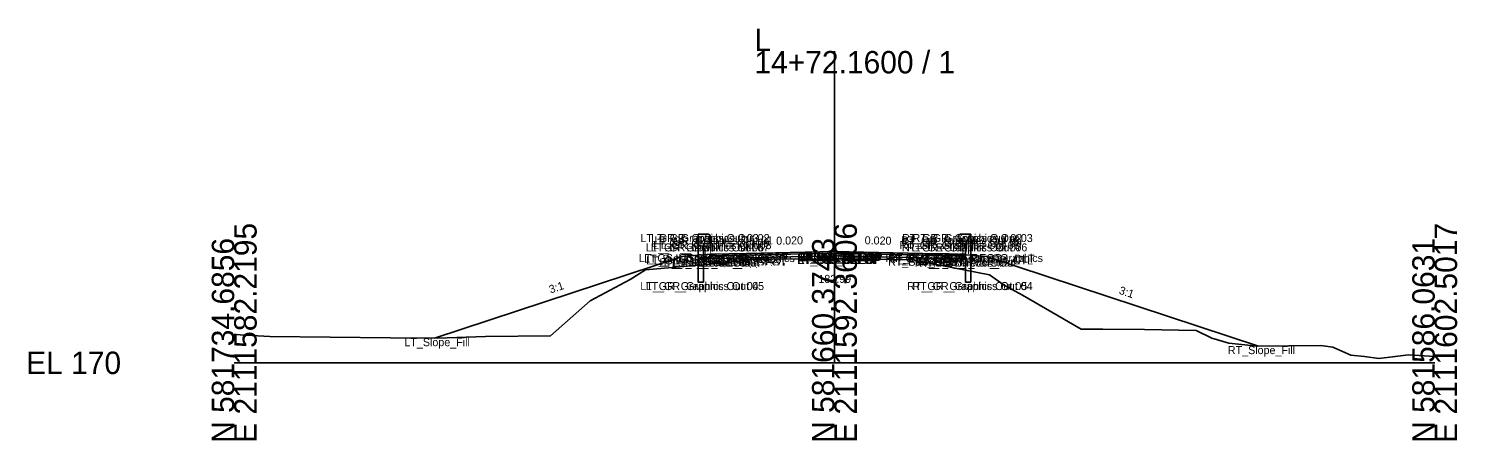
# Model space of a CAD drawing. Extents: x -26 to 3453, y -333 to 9539.
# Drawn here: x 3274.3 to 3452.8, y 490.3 to 541.8 of the extents above; entities that cross this region are included whole.
import ezdxf

# ---------------------------------------------------------------- set-up
doc = ezdxf.new("R2010")
doc.units = 0
for name, color, linetype in [('Default', 7, 'Continuous'), ('Exist Cross Section Cell', 7, 'Continuous'), ('Exist XS Ground Line', 7, 'Continuous'), ('Prop CMT Guardrail Graphics', 7, 'Continuous'), ('Prop CMT Pvmt Course 1', 7, 'Continuous'), ('Prop CMT Pvmt Course 2', 7, 'Continuous'), ('Prop CMT Pvmt Course 3', 7, 'Continuous'), ('Prop CMT Pvmt Surface', 7, 'Continuous'), ('Prop CMT Pvmt Surface Shoulder', 7, 'Continuous'), ('Prop CMT Shld Paved Course 1', 7, 'Continuous'), ('Prop CMT Shld Paved Course 2', 7, 'Continuous'), ('Prop CMT Shld Paved Course 3', 7, 'Continuous'), ('Prop CMT Slope Grass', 7, 'Continuous'), ('Prop CMT Subgrade Earthwork', 7, 'Continuous'), ('Prop XS SE Text', 7, 'Continuous'), ('Prop XS Side Slope Text', 7, 'Continuous'), ('Scratch_Level_0', 7, 'Continuous')]:
    doc.layers.add(name, color=color, linetype=linetype)

msp = doc.modelspace()

# ---------------------------------------------------------------- linework, layer by layer
at = {"layer": 'Exist Cross Section Cell'}
for p, q in [((3375, 500), (3375, 538.96)), ((3300, 500), (3375, 500)), ((3375, 500), (3450, 500))]:
    msp.add_line(p, q, dxfattribs=at)
at = {"layer": 'Exist XS Ground Line'}
msp.add_lwpolyline([(3300, 503.55), (3304.47, 503.31), (3319.51, 503.13), (3325.42, 503.08), (3331.39, 503.27), (3339.52, 503.36), (3344.49, 507.76), (3349.48, 510.4), (3351.38, 511.61), (3359.51, 512.34), (3365, 512.95), (3367.11, 512.96), (3374.8, 512.99), (3376.91, 512.98), (3384.74, 512.88), (3386.65, 512.51), (3394.36, 510.98), (3396.22, 509.7), (3398.48, 508.44), (3405.82, 504.2), (3408.53, 504.2), (3413.76, 504.16), (3420.21, 504.03), (3422.17, 503.07), (3424.27, 502.47), (3427.86, 502.09), (3435.69, 502.18), (3436.06, 502.12), (3437.26, 501.96), (3439.52, 500.94), (3441.23, 500.78), (3443.01, 500.54), (3444.72, 500.75), (3446.74, 500.99), (3450, 500.81)], dxfattribs=at)
at = {"layer": 'Prop CMT Guardrail Graphics'}
for points in [[(3357.97, 510.09), (3357.97, 516.09)], [(3357.97, 516.09), (3359.3, 516.09), (3359.57, 515.79)], [(3392.03, 516.09), (3390.7, 516.09), (3390.43, 515.79)], [(3392.03, 510.09), (3392.03, 516.09)], [(3359.57, 515.21), (3359.3, 514.92), (3358.64, 514.92)], [(3358.64, 514.92), (3358.64, 510.09)], [(3359.57, 515.79), (3359.3, 515.5)], [(3359.3, 515.5), (3359.57, 515.21)], [(3390.43, 515.79), (3390.7, 515.5)], [(3390.7, 515.5), (3390.43, 515.21)], [(3390.43, 515.21), (3390.7, 514.92), (3391.36, 514.92)], [(3391.36, 514.92), (3391.36, 510.09)], [(3358.64, 510.09), (3357.97, 510.09)], [(3391.36, 510.09), (3392.03, 510.09)]]:
    msp.add_lwpolyline(points, dxfattribs=at)
at = {"layer": 'Prop CMT Pvmt Course 1'}
for points in [[(3375, 513.9), (3364, 513.68)], [(3364, 513.47), (3375, 513.69)], [(3364, 513.68), (3364, 513.47)], [(3375, 513.69), (3375, 513.9)], [(3375, 513.9), (3386, 513.68)], [(3375, 513.69), (3375, 513.9)], [(3386, 513.47), (3375, 513.69)], [(3386, 513.68), (3386, 513.47)]]:
    msp.add_lwpolyline(points, dxfattribs=at)
msp.add_lwpolyline([(3375, 513.69), (3375, 513.77), (3375, 513.77), (3375, 513.69)], close=True, dxfattribs=at)
msp.add_lwpolyline([(3375, 513.69), (3375, 513.77), (3375, 513.77), (3375, 513.69)], close=True, dxfattribs=at)
at = {"layer": 'Prop CMT Pvmt Course 2'}
for points in [[(3375, 513.69), (3364, 513.47)], [(3364, 513.47), (3364, 513.13)], [(3364, 513.13), (3375, 513.35)], [(3375, 513.35), (3375, 513.69)], [(3375, 513.35), (3375, 513.69)], [(3375, 513.69), (3386, 513.47)], [(3386, 513.13), (3375, 513.35)], [(3386, 513.47), (3386, 513.13)]]:
    msp.add_lwpolyline(points, dxfattribs=at)
at = {"layer": 'Prop CMT Pvmt Course 3'}
for points in [[(3375, 513.35), (3364, 513.13)], [(3364, 513.13), (3375, 513.35)], [(3364, 513.13), (3364, 513.13)], [(3375, 513.35), (3375, 513.35)], [(3375, 513.35), (3386, 513.13)], [(3386, 513.13), (3375, 513.35)], [(3375, 513.35), (3375, 513.35)], [(3386, 513.13), (3386, 513.13)]]:
    msp.add_lwpolyline(points, dxfattribs=at)
at = {"layer": 'Prop CMT Pvmt Surface'}
for points in [[(3375, 513.9), (3364, 513.68)], [(3375, 513.9), (3386, 513.68)]]:
    msp.add_lwpolyline(points, dxfattribs=at)
at = {"layer": 'Prop CMT Pvmt Surface Shoulder'}
for points in [[(3364, 513.68), (3359.58, 513.59)], [(3386, 513.68), (3390.42, 513.59)]]:
    msp.add_lwpolyline(points, dxfattribs=at)
at = {"layer": 'Prop CMT Shld Paved Course 1'}
for points in [[(3364, 513.68), (3359.58, 513.59), (3359.37, 513.37)], [(3359.37, 513.37), (3364, 513.47)], [(3364, 513.47), (3364, 513.68)], [(3386, 513.68), (3390.42, 513.59), (3390.63, 513.37)], [(3386, 513.47), (3386, 513.68)], [(3390.63, 513.37), (3386, 513.47)]]:
    msp.add_lwpolyline(points, dxfattribs=at)
at = {"layer": 'Prop CMT Shld Paved Course 2'}
for points in [[(3364, 513.47), (3359.37, 513.37), (3359.03, 513.03)], [(3359.03, 513.03), (3364, 513.13)], [(3364, 513.13), (3364, 513.47)], [(3386, 513.47), (3390.63, 513.37), (3390.97, 513.03)], [(3386, 513.13), (3386, 513.47)], [(3390.97, 513.03), (3386, 513.13)]]:
    msp.add_lwpolyline(points, dxfattribs=at)
at = {"layer": 'Prop CMT Shld Paved Course 3'}
for points in [[(3364, 513.13), (3359.03, 513.03)], [(3359.03, 513.03), (3364, 513.13)], [(3359.03, 513.03), (3359.03, 513.03), (3359.03, 513.03)], [(3364, 513.13), (3364, 513.13)], [(3386, 513.13), (3390.97, 513.03)], [(3390.97, 513.03), (3386, 513.13)], [(3386, 513.13), (3386, 513.13)], [(3390.97, 513.03), (3390.97, 513.03), (3390.97, 513.03)]]:
    msp.add_lwpolyline(points, dxfattribs=at)
at = {"layer": 'Prop CMT Slope Grass'}
for points in [[(3356, 513.3), (3325.03, 503.08)], [(3359.57, 513.59), (3356, 513.3)], [(3359.58, 513.59), (3359.57, 513.59)], [(3390.42, 513.59), (3390.43, 513.59)], [(3390.43, 513.59), (3394, 513.3)], [(3394, 513.3), (3427.98, 502.09)]]:
    msp.add_lwpolyline(points, dxfattribs=at)
at = {"layer": 'Prop CMT Subgrade Earthwork'}
for points in [[(3359.03, 513.03), (3358.56, 513.51)], [(3364, 513.13), (3359.03, 513.03)], [(3375, 513.35), (3364, 513.13)], [(3375, 513.35), (3386, 513.13)], [(3386, 513.13), (3390.97, 513.03)], [(3390.97, 513.03), (3391.44, 513.51)]]:
    msp.add_lwpolyline(points, dxfattribs=at)

# ---------------------------------------------------------------- texts
at = {"layer": 'Default'}
msp.add_text('-', height=0.0001, dxfattribs=at).set_placement((3300, 500))
at = {"layer": 'Exist Cross Section Cell'}
for s, p in [('L', (3365, 538.96)), ('14+72.1600 / 1', (3365, 536.16)), ('EL 170', (3274, 498.6))]:
    msp.add_text(s, height=2.8, dxfattribs=at).set_placement(p)
for s, p in [('E 2111582.2195', (3302.8, 490)), ('E 2111592.3606', (3377.8, 490)), ('E 2111602.5017', (3452.8, 490)), ('N 581734.6856', (3300, 490)), ('N 581660.3743', (3375, 490)), ('N 581586.0631', (3450, 490))]:
    msp.add_text(s, height=2.8, rotation=90, dxfattribs=at).set_placement(p)
at = {"layer": 'Exist XS Ground Line'}
msp.add_text('182.99', height=1, dxfattribs=at).set_placement((3372.99, 509.99))
at = {"layer": 'Prop XS SE Text'}
for rotation, p in [(1.1458, (3367.73, 514.75)), (358.8542, (3378.77, 514.82))]:
    msp.add_text('0.020', height=1, rotation=rotation, dxfattribs=at).set_placement(p)
at = {"layer": 'Prop XS Side Slope Text'}
for rotation, p in [(18.2629, (3339.53, 508.66)), (341.7371, (3410.47, 508.65))]:
    msp.add_text('3:1', height=1, rotation=rotation, dxfattribs=at).set_placement(p)
at = {"layer": 'Scratch_Level_0'}
for s, p in [('LT_GR_Graphics Out 03', (3350.75, 515.09)), ('LT_GR_Graphics Out 02', (3352.1, 515.09)), ('RT_GR_Graphics Out 02', (3383.44, 515.09)), ('RT_GR_Graphics Out 03', (3384.76, 515.09)), ('LT_GR_Graphics Out 06', (3351.41, 513.92)), ('LT_GR_Graphics Out 07', (3352.06, 513.92)), ('LT_GR_Graphics Out 09', (3352.08, 514.5)), ('LT_GR_Graphics Out 08', (3352.34, 514.21)), ('LT_GR_Graphics Out 01', (3352.52, 514.79)), ('RT_GR_Graphics Out 08', (3383.14, 514.21)), ('RT_GR_Graphics Out 01', (3383.31, 514.79)), ('RT_GR_Graphics Out 07', (3383.4, 513.92)), ('RT_GR_Graphics Out 09', (3383.41, 514.5)), ('RT_GR_Graphics Out 06', (3384.08, 513.92)), ('LT_GS_OS_GR_Face_Graphics', (3350.57, 512.59)), ('LT_Sub_Trench_Out_DLT', (3351.21, 512.51)), ('LT_GS_OS_CTL', (3351.46, 512.3)), ('LT_Sub_Trench_Out', (3353.14, 512.03)), ('LT_PS3_Shelf_Out', (3353.69, 512.03)), ('LT_PS3_OEOP', (3354.82, 512.03)), ('LT_PS2_OEOP', (3355.16, 512.37)), ('LT_PS1_OEOP', (3355.49, 512.59)), ('LT_PV2_OEOT', (3359.75, 512.47)), ('LT_PV3_OEOT', (3359.75, 512.13)), ('LT_Sub_OEOT', (3359.77, 512.13)), ('LT_PV1_OEOT', (3359.87, 512.68)), ('RT_PV2_OEEOP', (3370.33, 512.69)), ('RT_PV3_OEEOP', (3370.33, 512.35)), ('RT_Sub_OEEOP', (3370.36, 512.35)), ('LT_PV2_OEEOP', (3370.39, 512.69)), ('LT_PV3_OEEOP', (3370.39, 512.35)), ('LT_Sub_OEEOP', (3370.42, 512.35)), ('RT_PV1_OEEOP', (3370.45, 512.77)), ('LT_PV1_OEEOP', (3370.51, 512.77)), ('RT_PV2_IEEOP', (3370.71, 512.69)), ('LT_PV2_IEEOP', (3370.77, 512.69)), ('RT_PV1_IEEOP', (3370.83, 512.77)), ('LT_PV1_IEEOP', (3370.89, 512.77)), ('PV2_PGL', (3372.35, 512.69)), ('PV1_PGL', (3372.47, 512.9)), ('RT_GS_OS_GR_Face_Graphics', (3381.36, 512.59)), ('RT_PV2_OEOT', (3381.69, 512.47)), ('RT_PV3_OEOT', (3381.69, 512.13)), ('RT_Sub_OEOT', (3381.71, 512.13)), ('RT_PV1_OEOT', (3381.81, 512.68)), ('RT_Sub_Trench_Out_DLT', (3384.03, 512.51)), ('RT_Sub_Trench_Out', (3385.02, 512.03)), ('RT_PS3_Shelf_Out', (3385.57, 512.03)), ('RT_PS1_OEOP', (3386.26, 512.59)), ('RT_PS2_OEOP', (3386.36, 512.37)), ('RT_PS3_OEOP', (3386.7, 512.03)), ('RT_GS_OS_CTL', (3389.4, 512.3)), ('LT_GR_Graphics Out 04', (3350.74, 509.09)), ('LT_GR_Graphics Out 05', (3351.41, 509.09)), ('RT_GR_Graphics Out 05', (3384.08, 509.09)), ('RT_GR_Graphics Out 04', (3384.74, 509.09)), ('LT_Slope_Fill', (3321.27, 502.08)), ('RT_Slope_Fill', (3424.16, 501.09))]:
    msp.add_text(s, height=1, dxfattribs=at).set_placement(p)

doc.saveas('drawing.dxf')
